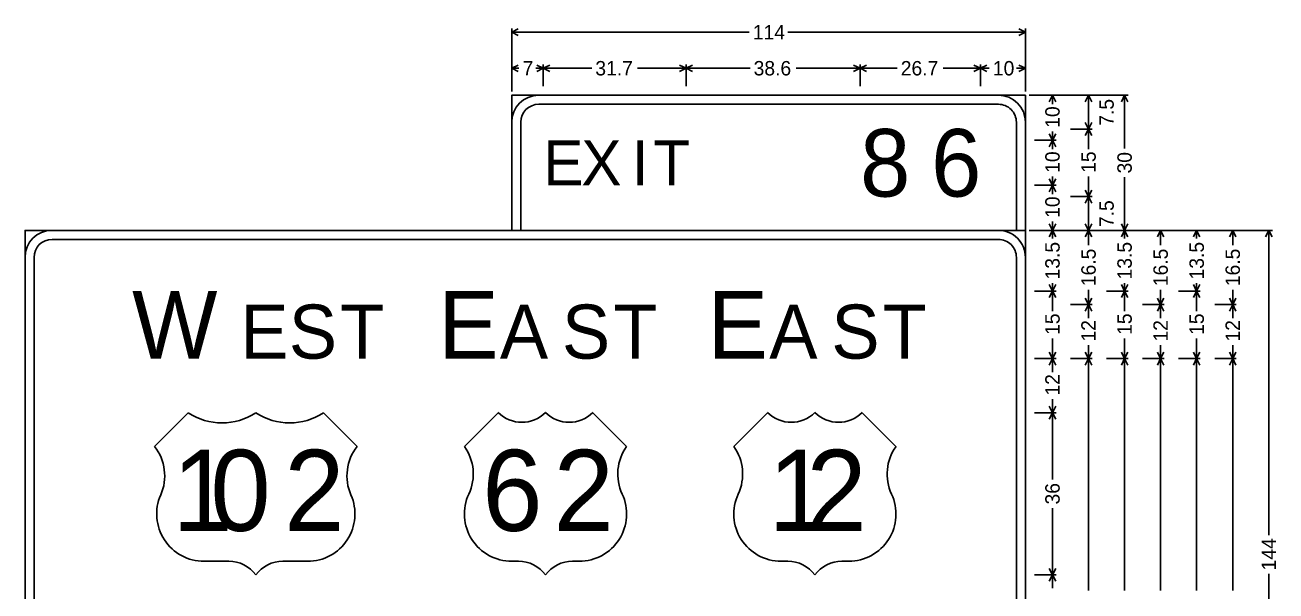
# Model space of a CAD drawing. Extents: x 667331 to 731245, y 738830 to 753817.
# Drawn here: x 719819.9 to 720236.3, y 748879.1 to 749067.6 of the extents above; entities that cross this region are included whole.
import ezdxf

# ---------------------------------------------------------------- set-up
doc = ezdxf.new("R2010")
doc.units = 0
doc.layers.add('R_SIGN', color=7, linetype='Continuous')

msp = doc.modelspace()

# ---------------------------------------------------------------- linework, layer by layer
at = {"layer": 'R_SIGN'}
for p, q in [((719981.9, 749066.43), (719981.9, 749045.43)), ((719984.05, 749066.3), (719981.9, 749065.23)), ((720150.76, 749066.3), (720152.9, 749065.23)), ((720152.9, 749066.43), (720152.9, 749045.43)), ((720060.96, 749065.23), (719981.9, 749065.23)), ((719984.05, 749064.15), (719981.9, 749065.23)), ((720073.84, 749065.23), (720152.9, 749065.23)), ((720150.76, 749064.15), (720152.9, 749065.23)), ((719981.9, 749054.43), (719981.9, 749047.23)), ((719984.05, 749054.3), (719981.9, 749053.23)), ((719990.26, 749054.3), (719992.4, 749053.23)), ((719992.4, 749054.43), (719992.4, 749047.23)), ((719994.55, 749054.3), (719992.4, 749053.23)), ((720037.81, 749054.3), (720039.95, 749053.23)), ((720039.95, 749054.43), (720039.95, 749047.23)), ((720042.1, 749054.3), (720039.95, 749053.23)), ((720095.71, 749054.3), (720097.86, 749053.23)), ((720097.86, 749054.43), (720097.86, 749047.23)), ((720100.01, 749054.3), (720097.86, 749053.23)), ((720135.76, 749054.3), (720137.9, 749053.23)), ((720137.9, 749054.43), (720137.9, 749047.23)), ((720137.9, 749054.43), (720137.9, 749047.23)), ((720140.05, 749054.3), (720137.9, 749053.23)), ((720150.76, 749054.3), (720152.9, 749053.23)), ((720152.9, 749054.43), (720152.9, 749047.23)), ((719984.33, 749053.23), (719981.9, 749053.23)), ((719984.05, 749052.15), (719981.9, 749053.23)), ((719989.97, 749053.23), (719992.4, 749053.23)), ((719990.26, 749052.15), (719992.4, 749053.23)), ((720008.54, 749053.23), (719992.4, 749053.23)), ((719994.55, 749052.15), (719992.4, 749053.23)), ((720023.81, 749053.23), (720039.95, 749053.23)), ((720037.81, 749052.15), (720039.95, 749053.23)), ((720061.23, 749053.23), (720039.95, 749053.23)), ((720042.1, 749052.15), (720039.95, 749053.23)), ((720076.58, 749053.23), (720097.86, 749053.23)), ((720095.71, 749052.15), (720097.86, 749053.23)), ((720110.2, 749053.23), (720097.86, 749053.23)), ((720100.01, 749052.15), (720097.86, 749053.23)), ((720125.56, 749053.23), (720137.9, 749053.23)), ((720135.76, 749052.15), (720137.9, 749053.23)), ((720140.87, 749053.23), (720137.9, 749053.23)), ((720140.05, 749052.15), (720137.9, 749053.23)), ((720149.93, 749053.23), (720152.9, 749053.23)), ((720150.76, 749052.15), (720152.9, 749053.23)), ((720187.1, 749044.23), (720154.1, 749044.23)), ((720163.1, 749044.23), (720155.9, 749044.23)), ((720160.83, 749042.08), (720161.9, 749044.23)), ((720161.9, 749041.26), (720161.9, 749044.23)), ((720162.98, 749042.08), (720161.9, 749044.23)), ((720175.1, 749044.23), (720167.9, 749044.23)), ((720172.83, 749042.08), (720173.9, 749044.23)), ((720173.9, 749038.6), (720173.9, 749044.23)), ((720174.98, 749042.08), (720173.9, 749044.23)), ((720184.83, 749042.08), (720185.9, 749044.23)), ((720185.9, 749026.47), (720185.9, 749044.23)), ((720186.98, 749042.08), (720185.9, 749044.23)), ((720173.9, 749038.6), (720173.9, 749032.98)), ((720175.1, 749032.98), (720167.9, 749032.98)), ((720172.83, 749035.12), (720173.9, 749032.98)), ((720172.83, 749030.83), (720173.9, 749032.98)), ((720174.98, 749035.12), (720173.9, 749032.98)), ((720173.9, 749026.27), (720173.9, 749032.98)), ((720174.98, 749030.83), (720173.9, 749032.98)), ((720163.1, 749029.23), (720155.9, 749029.23)), ((720160.83, 749031.37), (720161.9, 749029.23)), ((720160.83, 749027.08), (720161.9, 749029.23)), ((720161.9, 749032.2), (720161.9, 749029.23)), ((720162.98, 749031.37), (720161.9, 749029.23)), ((720161.9, 749026.26), (720161.9, 749029.23)), ((720162.98, 749027.08), (720161.9, 749029.23)), ((720160.83, 749016.37), (720161.9, 749014.23)), ((720161.9, 749017.2), (720161.9, 749014.23)), ((720162.98, 749016.37), (720161.9, 749014.23)), ((720173.9, 749017.19), (720173.9, 749010.48)), ((720185.9, 749016.98), (720185.9, 748999.23)), ((720163.1, 749014.23), (720155.9, 749014.23)), ((720163.1, 749014.23), (720155.9, 749014.23)), ((720160.83, 749012.08), (720161.9, 749014.23)), ((720161.9, 749011.26), (720161.9, 749014.23)), ((720162.98, 749012.08), (720161.9, 749014.23)), ((720172.83, 749012.62), (720173.9, 749010.48)), ((720174.98, 749012.62), (720173.9, 749010.48)), ((720175.1, 749010.48), (720167.9, 749010.48)), ((720175.1, 749010.48), (720167.9, 749010.48)), ((720172.83, 749008.33), (720173.9, 749010.48)), ((720173.9, 749004.85), (720173.9, 749010.48)), ((720174.98, 749008.33), (720173.9, 749010.48)), ((720173.9, 749004.85), (720173.9, 748999.23)), ((720160.83, 749001.37), (720161.9, 748999.23)), ((720161.9, 749002.2), (720161.9, 748999.23)), ((720162.98, 749001.37), (720161.9, 748999.23)), ((720172.83, 749001.37), (720173.9, 748999.23)), ((720174.98, 749001.37), (720173.9, 748999.23)), ((720184.83, 749001.37), (720185.9, 748999.23)), ((720186.98, 749001.37), (720185.9, 748999.23)), ((720235.1, 748999.23), (720154.1, 748999.23)), ((720187.1, 748999.23), (720154.1, 748999.23)), ((720163.1, 748999.23), (720155.9, 748999.23)), ((720163.1, 748999.23), (720155.9, 748999.23)), ((720160.83, 748997.08), (720161.9, 748999.23)), ((720161.9, 748996.55), (720161.9, 748999.23)), ((720162.98, 748997.08), (720161.9, 748999.23)), ((720175.1, 748999.23), (720167.9, 748999.23)), ((720175.1, 748999.23), (720167.9, 748999.23)), ((720172.83, 748997.08), (720173.9, 748999.23)), ((720173.9, 748994.3), (720173.9, 748999.23)), ((720174.98, 748997.08), (720173.9, 748999.23)), ((720187.1, 748999.23), (720179.9, 748999.23)), ((720184.83, 748997.08), (720185.9, 748999.23)), ((720185.9, 748996.55), (720185.9, 748999.23)), ((720186.98, 748997.08), (720185.9, 748999.23)), ((720199.1, 748999.23), (720191.9, 748999.23)), ((720196.83, 748997.08), (720197.9, 748999.23)), ((720197.9, 748994.3), (720197.9, 748999.23)), ((720198.98, 748997.08), (720197.9, 748999.23)), ((720211.1, 748999.23), (720203.9, 748999.23)), ((720208.83, 748997.08), (720209.9, 748999.23)), ((720209.9, 748996.55), (720209.9, 748999.23)), ((720210.98, 748997.08), (720209.9, 748999.23)), ((720223.1, 748999.23), (720215.9, 748999.23)), ((720220.83, 748997.08), (720221.9, 748999.23)), ((720221.9, 748994.3), (720221.9, 748999.23)), ((720222.98, 748997.08), (720221.9, 748999.23)), ((720232.83, 748997.08), (720233.9, 748999.23)), ((720233.9, 748897.67), (720233.9, 748999.23)), ((720234.98, 748997.08), (720233.9, 748999.23)), ((720163.1, 748979.01), (720155.9, 748979.01)), ((720160.83, 748981.16), (720161.9, 748979.01)), ((720160.83, 748976.87), (720161.9, 748979.01)), ((720161.9, 748981.69), (720161.9, 748979.01)), ((720162.98, 748981.16), (720161.9, 748979.01)), ((720161.9, 748972.31), (720161.9, 748979.01)), ((720162.98, 748976.87), (720161.9, 748979.01)), ((720173.9, 748979.44), (720173.9, 748974.51)), ((720187.1, 748979.01), (720179.9, 748979.01)), ((720184.83, 748981.16), (720185.9, 748979.01)), ((720184.83, 748976.87), (720185.9, 748979.01)), ((720185.9, 748981.69), (720185.9, 748979.01)), ((720186.98, 748981.16), (720185.9, 748979.01)), ((720185.9, 748972.31), (720185.9, 748979.01)), ((720186.98, 748976.87), (720185.9, 748979.01)), ((720197.9, 748979.44), (720197.9, 748974.51)), ((720211.1, 748979.01), (720203.9, 748979.01)), ((720208.83, 748981.16), (720209.9, 748979.01)), ((720208.83, 748976.87), (720209.9, 748979.01)), ((720209.9, 748981.69), (720209.9, 748979.01)), ((720210.98, 748981.16), (720209.9, 748979.01)), ((720209.9, 748972.31), (720209.9, 748979.01)), ((720210.98, 748976.87), (720209.9, 748979.01)), ((720221.9, 748979.44), (720221.9, 748974.51)), ((720175.1, 748974.51), (720167.9, 748974.51)), ((720172.83, 748976.66), (720173.9, 748974.51)), ((720172.83, 748972.37), (720173.9, 748974.51)), ((720174.98, 748976.66), (720173.9, 748974.51)), ((720173.9, 748970.03), (720173.9, 748974.51)), ((720174.98, 748972.37), (720173.9, 748974.51)), ((720199.1, 748974.51), (720191.9, 748974.51)), ((720196.83, 748976.66), (720197.9, 748974.51)), ((720196.83, 748972.37), (720197.9, 748974.51)), ((720198.98, 748976.66), (720197.9, 748974.51)), ((720197.9, 748970.03), (720197.9, 748974.51)), ((720198.98, 748972.37), (720197.9, 748974.51)), ((720223.1, 748974.51), (720215.9, 748974.51)), ((720220.83, 748976.66), (720221.9, 748974.51)), ((720220.83, 748972.37), (720221.9, 748974.51)), ((720222.98, 748976.66), (720221.9, 748974.51)), ((720221.9, 748970.03), (720221.9, 748974.51)), ((720222.98, 748972.37), (720221.9, 748974.51)), ((720161.9, 748963.22), (720161.9, 748956.51)), ((720185.9, 748963.22), (720185.9, 748956.51)), ((720209.9, 748963.22), (720209.9, 748956.51)), ((720160.83, 748958.66), (720161.9, 748956.51)), ((720162.98, 748958.66), (720161.9, 748956.51)), ((720172.83, 748958.66), (720173.9, 748956.51)), ((720173.9, 748961), (720173.9, 748956.51)), ((720174.98, 748958.66), (720173.9, 748956.51)), ((720184.83, 748958.66), (720185.9, 748956.51)), ((720186.98, 748958.66), (720185.9, 748956.51)), ((720196.83, 748958.66), (720197.9, 748956.51)), ((720197.9, 748961), (720197.9, 748956.51)), ((720198.98, 748958.66), (720197.9, 748956.51)), ((720208.83, 748958.66), (720209.9, 748956.51)), ((720210.98, 748958.66), (720209.9, 748956.51)), ((720220.83, 748958.66), (720221.9, 748956.51)), ((720221.9, 748961), (720221.9, 748956.51)), ((720222.98, 748958.66), (720221.9, 748956.51)), ((720163.1, 748956.51), (720155.9, 748956.51)), ((720160.83, 748954.37), (720161.9, 748956.51)), ((720161.9, 748952.03), (720161.9, 748956.51)), ((720162.98, 748954.37), (720161.9, 748956.51)), ((720175.1, 748956.51), (720167.9, 748956.51)), ((720175.1, 748956.51), (720167.9, 748956.51)), ((720172.83, 748954.37), (720173.9, 748956.51)), ((720173.9, 748879.23), (720173.9, 748956.51)), ((720174.98, 748954.37), (720173.9, 748956.51)), ((720187.1, 748956.51), (720179.9, 748956.51)), ((720187.1, 748956.51), (720179.9, 748956.51)), ((720184.83, 748954.37), (720185.9, 748956.51)), ((720185.9, 748879.23), (720185.9, 748956.51)), ((720186.98, 748954.37), (720185.9, 748956.51)), ((720199.1, 748956.51), (720191.9, 748956.51)), ((720199.1, 748956.51), (720191.9, 748956.51)), ((720196.83, 748954.37), (720197.9, 748956.51)), ((720197.9, 748879.23), (720197.9, 748956.51)), ((720198.98, 748954.37), (720197.9, 748956.51)), ((720211.1, 748956.51), (720203.9, 748956.51)), ((720211.1, 748956.51), (720203.9, 748956.51)), ((720208.83, 748954.37), (720209.9, 748956.51)), ((720209.9, 748879.23), (720209.9, 748956.51)), ((720210.98, 748954.37), (720209.9, 748956.51)), ((720223.1, 748956.51), (720215.9, 748956.51)), ((720223.1, 748956.51), (720215.9, 748956.51)), ((720220.83, 748954.37), (720221.9, 748956.51)), ((720221.9, 748879.23), (720221.9, 748956.51)), ((720222.98, 748954.37), (720221.9, 748956.51)), ((720161.9, 748943), (720161.9, 748938.51)), ((719874.23, 748938.51), (719862.98, 748927.26)), ((719930.48, 748927.26), (719919.23, 748938.51)), ((719977.4, 748938.51), (719966.15, 748927.26)), ((720020.15, 748927.26), (720008.9, 748938.51)), ((720067.07, 748938.51), (720055.82, 748927.26)), ((720109.82, 748927.26), (720098.57, 748938.51)), ((720163.1, 748938.51), (720155.9, 748938.51)), ((720160.83, 748940.66), (720161.9, 748938.51)), ((720160.83, 748936.37), (720161.9, 748938.51)), ((720162.98, 748940.66), (720161.9, 748938.51)), ((720161.9, 748916.3), (720161.9, 748938.51)), ((720162.98, 748936.37), (720161.9, 748938.51)), ((720161.9, 748906.73), (720161.9, 748884.51)), ((719879.48, 748889.01), (719887.73, 748889.01)), ((719905.73, 748889.01), (719913.98, 748889.01)), ((719981.9, 748889.01), (719984.15, 748889.01)), ((720002.15, 748889.01), (720004.4, 748889.01)), ((720071.57, 748889.01), (720073.82, 748889.01)), ((720091.82, 748889.01), (720094.07, 748889.01)), ((720163.1, 748884.51), (720155.9, 748884.51)), ((720160.83, 748886.66), (720161.9, 748884.51)), ((720160.83, 748882.37), (720161.9, 748884.51)), ((720162.98, 748886.66), (720161.9, 748884.51)), ((720161.9, 748880.03), (720161.9, 748884.51)), ((720162.98, 748882.37), (720161.9, 748884.51)), ((720233.9, 748884.79), (720233.9, 748783.23))]:
    msp.add_line(p, q, dxfattribs=at)
for points in [[(719981.9, 748999.23), (720152.9, 748999.23), (720152.9, 749044.23), (719981.9, 749044.23), (719981.9, 748999.23), (719981.9, 748999.23)], [(719990.9, 749044.23), (720143.9, 749044.23)], [(720143.9, 749041.23), (719990.9, 749041.23)], [(719981.9, 748999.23), (719981.9, 749035.23)], [(719984.9, 749035.23), (719984.9, 748999.23)], [(720149.9, 748999.23), (720149.9, 749035.23)], [(720152.9, 749035.23), (720152.9, 748999.23)], [(719819.9, 748783.23), (720152.9, 748783.23), (720152.9, 748999.23), (719819.9, 748999.23), (719819.9, 748783.23), (719819.9, 748783.23)], [(719828.9, 748999.23), (720143.9, 748999.23)], [(720143.9, 748996.23), (719828.9, 748996.23)], [(719819.9, 748783.23), (719819.9, 748990.23)], [(719822.9, 748990.23), (719822.9, 748783.23)], [(720149.9, 748783.23), (720149.9, 748990.23)], [(720152.9, 748990.23), (720152.9, 748783.23)]]:
    msp.add_lwpolyline(points, dxfattribs=at)
for centre, radius, start, end in [((719990.9, 749035.23), 9, 90.0002, 179.9998), ((719990.9, 749035.23), 6, 90.0002, 179.9998), ((720143.9, 749035.23), 9, 0, 90.0002), ((720143.9, 749035.23), 6, 0, 90.0002), ((719828.9, 748990.23), 9, 90.0002, 179.9998), ((719828.9, 748990.23), 6, 90.0002, 179.9998), ((720143.9, 748990.23), 9, 0, 90.0002), ((720143.9, 748990.23), 6, 0, 90.0002), ((719885.48, 748955.35), 20.25, 236.2511, 303.749), ((719907.98, 748955.35), 20.25, 236.2511, 303.749), ((719985.28, 748946.55), 11.25, 225.5729, 314.4272), ((720001.03, 748946.55), 11.25, 225.5729, 314.4272), ((720074.95, 748946.55), 11.25, 225.5729, 314.4272), ((720090.7, 748946.55), 11.25, 225.5729, 314.4272), ((719850.65, 748917.46), 15.75, 336.2288, 38.491), ((719942.81, 748917.46), 15.75, 141.5085, 203.7713), ((719953.36, 748918.08), 15.75, 334.9895, 35.6629), ((720032.95, 748918.08), 15.75, 144.3372, 205.01), ((720043.03, 748918.08), 15.75, 334.9895, 35.6629), ((720122.62, 748918.08), 15.75, 144.3372, 205.01), ((719879.48, 748904.76), 15.75, 156.2284, 270.0001), ((719913.98, 748904.76), 15.75, 270.0001, 23.7711), ((719981.9, 748904.76), 15.75, 154.9897, 270.0001), ((720004.4, 748904.76), 15.75, 270.0001, 25.0104), ((720071.57, 748904.76), 15.75, 154.9897, 270.0001), ((720094.07, 748904.76), 15.75, 270.0001, 25.0104), ((719887.73, 748877.76), 11.25, 36.8699, 90.0002), ((719905.73, 748877.76), 11.25, 90.0002, 143.13), ((719984.15, 748877.76), 11.25, 36.8699, 90.0002), ((720002.15, 748877.76), 11.25, 90.0002, 143.13), ((720073.82, 748877.76), 11.25, 36.8699, 90.0002), ((720091.82, 748877.76), 11.25, 90.0002, 143.13)]:
    msp.add_arc(centre, radius, start, end, dxfattribs=at)

# ---------------------------------------------------------------- texts
for s, height, p in [('114', 4.8, (720062.16, 749062.83)), ('7', 4.8, (719985.53, 749050.83)), ('31.7', 4.8, (720009.74, 749050.83)), ('38.6', 4.8, (720062.43, 749050.83)), ('26.7', 4.8, (720111.4, 749050.83)), ('10', 4.8, (720142.07, 749050.83)), ('8', 22.5, (720097.86, 749010.48)), ('6', 22.5, (720121.5, 749010.48)), ('E', 15, (719992.4, 749014.23)), ('X', 15, (720005.08, 749014.23)), ('I', 15, (720021.85, 749014.23)), ('T', 15, (720029.02, 749014.23)), ('W', 22.5, (719855.55, 748956.51)), ('E', 22.5, (719957.48, 748956.51)), ('E', 22.5, (720047.15, 748956.51)), ('E', 18, (719891.55, 748956.51)), ('S', 18, (719907.71, 748956.51)), ('T', 18, (719924.8, 748956.51)), ('A', 18, (719977.97, 748956.51)), ('S', 18, (719998.62, 748956.51)), ('T', 18, (720015.7, 748956.51)), ('A', 18, (720067.64, 748956.51)), ('S', 18, (720088.29, 748956.51)), ('T', 18, (720105.37, 748956.51)), ('1', 27, (719868.92, 748899.14)), ('0', 27, (719881.61, 748899.14)), ('2', 27, (719906.18, 748899.14)), ('6', 27, (719972.09, 748899.14)), ('2', 27, (719995.85, 748899.14)), ('1', 27, (720067.3, 748899.14)), ('2', 27, (720079.99, 748899.14))]:
    msp.add_text(s, height=height, dxfattribs=at).set_placement(p)
for s, p in [('7.5', (720182.3, 749034.08)), ('10', (720164.3, 749033.4)), ('10', (720164.3, 749018.4)), ('15', (720176.3, 749018.39)), ('30', (720188.3, 749018.18)), ('10', (720164.3, 749003.4)), ('7.5', (720182.3, 749000.33)), ('13.5', (720164.3, 748982.89)), ('16.5', (720176.3, 748980.64)), ('13.5', (720188.3, 748982.89)), ('16.5', (720200.3, 748980.64)), ('13.5', (720212.3, 748982.89)), ('16.5', (720224.3, 748980.64)), ('15', (720164.3, 748964.42)), ('15', (720188.3, 748964.42)), ('15', (720212.3, 748964.42)), ('12', (720176.3, 748962.2)), ('12', (720200.3, 748962.2)), ('12', (720224.3, 748962.2)), ('12', (720164.3, 748944.2)), ('36', (720164.3, 748907.93)), ('144', (720236.3, 748885.99))]:
    msp.add_text(s, height=4.8, rotation=90.0002, dxfattribs=at).set_placement(p)

doc.saveas('drawing.dxf')
